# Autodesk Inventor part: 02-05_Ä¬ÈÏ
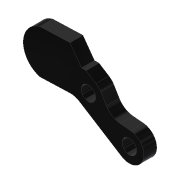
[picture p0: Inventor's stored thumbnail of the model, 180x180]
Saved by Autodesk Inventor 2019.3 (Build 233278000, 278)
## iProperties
Created: 2010-06
Part Number: 02-05_Ä¬ÈÏ
Material: Ogólny
Document SubType Name: Modeling
Designer: CADENGINEERING4
Density: 1 g/cm^3
Appearance: Gładki — czarny
Author: CADENGINEERING4
Revision Number: ÈÎºÎ
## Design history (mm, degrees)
feature "NONE"
node "Bryła1"
